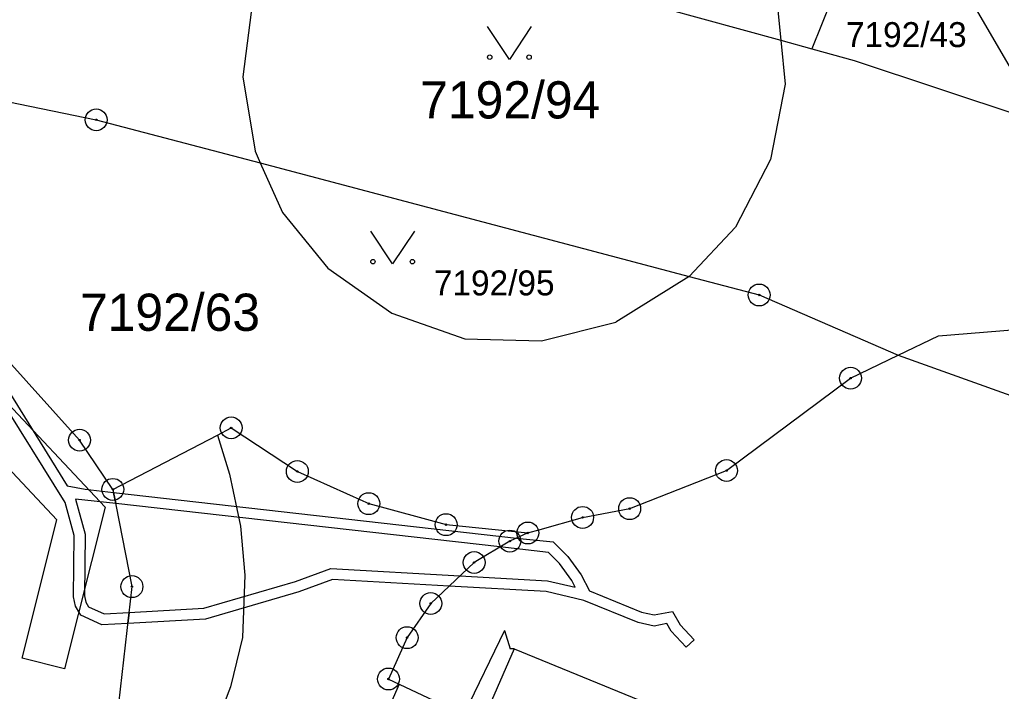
# Model space of a CAD drawing. Extents: x -593183 to -588034, y -1130415 to -1124994.
# Drawn here: x -592144.33 to -592099.52, y -1128222.06 to -1128191.38 of the extents above; entities that cross this region are included whole.
import ezdxf

# ---------------------------------------------------------------- set-up
doc = ezdxf.new("R2010")
doc.units = 0
for name, color, linetype in [('Vrstva 1', 7, 'Continuous'), ('Vrstva 18', 7, 'Continuous'), ('Vrstva 24', 7, 'Continuous'), ('Vrstva 25', 7, 'Continuous'), ('Vrstva 27', 7, 'Continuous'), ('Vrstva 4', 7, 'Continuous')]:
    doc.layers.add(name, color=color, linetype=linetype)

msp = doc.modelspace()

# ---------------------------------------------------------------- linework, layer by layer
at = {"layer": 'Vrstva 1'}
for p, q in [((-592189.56, -1128185.87), (-592140.83, -1128195.96)), ((-592131.54, -1128186.28), (-592109.58, -1128192.33)), ((-592133.68, -1128190.44), (-592134.14, -1128194)), ((-592101.16, -1128190.07), (-592099.01, -1128193.77)), ((-592109.73, -1128190.81), (-592109.58, -1128192.33)), ((-592107.29, -1128190.52), (-592108.17, -1128192.72)), ((-592109.58, -1128192.33), (-592109.39, -1128194.33)), ((-592109.58, -1128192.33), (-592108.17, -1128192.72)), ((-592108.17, -1128192.72), (-592106.24, -1128193.25)), ((-592106.24, -1128193.25), (-592094.48, -1128197.15)), ((-592134.14, -1128194), (-592133.58, -1128197.4)), ((-592109.39, -1128194.33), (-592110.06, -1128197.77)), ((-592140.83, -1128195.96), (-592133.34, -1128197.93)), ((-592133.58, -1128197.4), (-592133.34, -1128197.93)), ((-592133.34, -1128197.93), (-592132.32, -1128200.19)), ((-592133.34, -1128197.93), (-592113.76, -1128203.11)), ((-592110.06, -1128197.77), (-592111.65, -1128200.87)), ((-592132.32, -1128200.19), (-592130.26, -1128202.74)), ((-592111.65, -1128200.87), (-592113.76, -1128203.11)), ((-592130.26, -1128202.74), (-592127.34, -1128204.79)), ((-592113.76, -1128203.11), (-592117.11, -1128205.21)), ((-592113.76, -1128203.11), (-592110.57, -1128203.96)), ((-592110.57, -1128203.96), (-592104.23, -1128206.71)), ((-592127.34, -1128204.79), (-592124.01, -1128205.96)), ((-592120.5, -1128206.05), (-592117.11, -1128205.21)), ((-592099.59, -1128205.6), (-592095.83, -1128205.29)), ((-592102.39, -1128205.83), (-592099.59, -1128205.6)), ((-592124.01, -1128205.96), (-592120.5, -1128206.05)), ((-592104.23, -1128206.71), (-592102.39, -1128205.83)), ((-592141.59, -1128210.59), (-592145.26, -1128206.52)), ((-592106.4, -1128207.76), (-592104.23, -1128206.71)), ((-592104.23, -1128206.71), (-592056.76, -1128223.76)), ((-592112.06, -1128211.98), (-592106.4, -1128207.76)), ((-592135.3, -1128210.36), (-592134.67, -1128210.03)), ((-592134.67, -1128210.03), (-592131.65, -1128212.02)), ((-592140.07, -1128212.84), (-592141.59, -1128210.59)), ((-592140.07, -1128212.84), (-592135.3, -1128210.36)), ((-592135.3, -1128210.36), (-592134.74, -1128212.14)), ((-592131.65, -1128212.02), (-592128.66, -1128213.37)), ((-592116.48, -1128213.72), (-592112.06, -1128211.98)), ((-592134.74, -1128212.14), (-592134.25, -1128214.52)), ((-592140.07, -1128212.84), (-592139.2, -1128217.28)), ((-592128.66, -1128213.37), (-592128.39, -1128213.49)), ((-592128.39, -1128213.49), (-592124.86, -1128214.45)), ((-592118.63, -1128214.12), (-592116.48, -1128213.72)), ((-592120.56, -1128214.67), (-592118.63, -1128214.12)), ((-592134.25, -1128214.52), (-592134.05, -1128216.76)), ((-592124.86, -1128214.45), (-592121.13, -1128214.83)), ((-592121.13, -1128214.83), (-592120.56, -1128214.67)), ((-592121.13, -1128214.83), (-592121.95, -1128215.2)), ((-592121.95, -1128215.2), (-592123.58, -1128216.18)), ((-592123.58, -1128216.18), (-592125.56, -1128218.05)), ((-592134.05, -1128216.76), (-592134.15, -1128219.61)), ((-592139.2, -1128217.28), (-592139.81, -1128222.63)), ((-592125.56, -1128218.05), (-592126.64, -1128219.61)), ((-592134.15, -1128219.61), (-592134.7, -1128221.86)), ((-592126.64, -1128219.61), (-592127.49, -1128221.5)), ((-592122.2, -1128219.29), (-592124.05, -1128223.12)), ((-592122.2, -1128219.29), (-592121.93, -1128220.12)), ((-592121.75, -1128220.12), (-592121.93, -1128220.12)), ((-592121.75, -1128220.12), (-592095.77, -1128230.76)), ((-592134.7, -1128221.86), (-592143.3, -1128243.89)), ((-592127, -1128221.73), (-592128.21, -1128224.48)), ((-592127.49, -1128221.5), (-592127, -1128221.73)), ((-592127, -1128221.73), (-592124.05, -1128223.12))]:
    msp.add_line(p, q, dxfattribs=at)
at = {"layer": 'Vrstva 24'}
for centre, radius in [((-592140.83, -1128195.96), 0.5), ((-592140.83, -1128195.96), 0.0327), ((-592110.57, -1128203.96), 0.5), ((-592110.57, -1128203.96), 0.0327), ((-592106.4, -1128207.76), 0.5), ((-592106.4, -1128207.76), 0.0327), ((-592134.67, -1128210.03), 0.5), ((-592141.59, -1128210.59), 0.5), ((-592134.67, -1128210.03), 0.0327), ((-592141.59, -1128210.59), 0.0327), ((-592131.65, -1128212.02), 0.5), ((-592112.06, -1128211.98), 0.5), ((-592131.65, -1128212.02), 0.0327), ((-592112.06, -1128211.98), 0.0327), ((-592140.07, -1128212.84), 0.5), ((-592140.07, -1128212.84), 0.0327), ((-592128.39, -1128213.49), 0.5), ((-592116.48, -1128213.72), 0.5), ((-592128.39, -1128213.49), 0.0327), ((-592118.63, -1128214.12), 0.5), ((-592116.48, -1128213.72), 0.0327), ((-592124.86, -1128214.45), 0.5), ((-592118.63, -1128214.12), 0.0327), ((-592124.86, -1128214.45), 0.0327), ((-592121.95, -1128215.2), 0.5), ((-592121.13, -1128214.83), 0.5), ((-592121.13, -1128214.83), 0.0327), ((-592121.95, -1128215.2), 0.0327), ((-592123.58, -1128216.18), 0.5), ((-592123.58, -1128216.18), 0.0327), ((-592139.2, -1128217.28), 0.5), ((-592139.2, -1128217.28), 0.0327), ((-592125.56, -1128218.05), 0.5), ((-592125.56, -1128218.05), 0.0327), ((-592126.64, -1128219.61), 0.5), ((-592126.64, -1128219.61), 0.0327), ((-592127.49, -1128221.5), 0.5), ((-592127.49, -1128221.5), 0.0327)]:
    msp.add_circle(centre, radius, dxfattribs=at)
at = {"layer": 'Vrstva 25'}
for points in [[(-592120.97, -1128191.7), (-592121.97, -1128193.2), (-592122.97, -1128191.7)], [(-592126.3, -1128201.04), (-592127.3, -1128202.54), (-592128.3, -1128201.04)]]:
    msp.add_lwpolyline(points, dxfattribs=at)
for centre in [(-592122.87, -1128193.1), (-592121.07, -1128193.1), (-592128.2, -1128202.44), (-592126.4, -1128202.44)]:
    msp.add_circle(centre, 0.1, dxfattribs=at)
at = {"layer": 'Vrstva 27'}
for p, q in [((-592148.83, -1128201.93), (-592142.15, -1128212.67)), ((-592142.25, -1128213.44), (-592149.19, -1128202.29)), ((-592150.22, -1128203.23), (-592140.42, -1128213.65)), ((-592142.62, -1128214.23), (-592151.62, -1128204.65)), ((-592142.15, -1128212.67), (-592141.33, -1128212.83)), ((-592141.33, -1128212.83), (-592140.04, -1128212.98)), ((-592139.94, -1128213.49), (-592141.78, -1128213.29)), ((-592141.78, -1128213.29), (-592141.34, -1128214.88)), ((-592140.04, -1128212.98), (-592139.94, -1128213.49)), ((-592140.04, -1128212.98), (-592121.64, -1128215.06)), ((-592139.94, -1128213.49), (-592140.04, -1128212.98)), ((-592140.42, -1128213.65), (-592142.27, -1128221.03)), ((-592141.84, -1128214.94), (-592142.25, -1128213.44)), ((-592122.4, -1128215.47), (-592139.94, -1128213.49)), ((-592144.21, -1128220.55), (-592142.62, -1128214.23)), ((-592141.86, -1128217.74), (-592141.84, -1128214.94)), ((-592141.34, -1128214.88), (-592141.36, -1128217.7)), ((-592121.64, -1128215.06), (-592119.97, -1128215.24)), ((-592120.19, -1128215.72), (-592122.4, -1128215.47)), ((-592119.97, -1128215.24), (-592119.3, -1128215.9)), ((-592119.68, -1128216.22), (-592120.19, -1128215.72)), ((-592119.3, -1128215.9), (-592118.7, -1128216.74)), ((-592131.74, -1128217.04), (-592130.12, -1128216.46)), ((-592130.12, -1128216.46), (-592124.23, -1128216.79)), ((-592119.12, -1128217), (-592119.68, -1128216.22)), ((-592124.23, -1128216.79), (-592120.23, -1128217.01)), ((-592118.7, -1128216.74), (-592118.32, -1128217.48)), ((-592135.92, -1128218.26), (-592131.74, -1128217.04)), ((-592130.04, -1128216.96), (-592131.58, -1128217.52)), ((-592124.72, -1128217.26), (-592130.04, -1128216.96)), ((-592120.29, -1128217.51), (-592124.72, -1128217.26)), ((-592120.23, -1128217.01), (-592118.97, -1128217.31)), ((-592118.97, -1128217.31), (-592119.12, -1128217)), ((-592141.78, -1128218.17), (-592141.86, -1128217.74)), ((-592141.36, -1128217.7), (-592141.3, -1128217.99)), ((-592131.58, -1128217.52), (-592135.84, -1128218.76)), ((-592118.58, -1128217.92), (-592120.29, -1128217.51)), ((-592118.32, -1128217.48), (-592115.94, -1128218.44)), ((-592141.53, -1128218.58), (-592141.78, -1128218.17)), ((-592141.3, -1128217.99), (-592141.18, -1128218.2)), ((-592141.18, -1128218.2), (-592140.47, -1128218.53)), ((-592139.33, -1128218.46), (-592135.92, -1128218.26)), ((-592116.09, -1128218.92), (-592118.58, -1128217.92)), ((-592140.57, -1128219.03), (-592141.53, -1128218.58)), ((-592140.47, -1128218.53), (-592139.33, -1128218.46)), ((-592139.33, -1128218.46), (-592139.39, -1128218.97)), ((-592139.39, -1128218.97), (-592139.33, -1128218.46)), ((-592115.94, -1128218.44), (-592115.36, -1128218.57)), ((-592115.36, -1128218.57), (-592114.53, -1128218.41)), ((-592114.53, -1128218.41), (-592114.18, -1128219.02)), ((-592139.39, -1128218.97), (-592140.57, -1128219.03)), ((-592135.84, -1128218.76), (-592139.39, -1128218.97)), ((-592115.36, -1128219.08), (-592116.09, -1128218.92)), ((-592114.79, -1128218.97), (-592115.36, -1128219.08)), ((-592114.58, -1128219.32), (-592114.79, -1128218.97)), ((-592114.18, -1128219.02), (-592113.54, -1128219.71)), ((-592113.9, -1128220.05), (-592114.58, -1128219.32)), ((-592113.54, -1128219.71), (-592113.9, -1128220.05)), ((-592142.27, -1128221.03), (-592144.21, -1128220.55))]:
    msp.add_line(p, q, dxfattribs=at)
at = {"layer": 'Vrstva 4'}
msp.add_line((-592121.75, -1128220.12), (-592128.38, -1128235.33), dxfattribs=at)

# ---------------------------------------------------------------- texts
at = {"layer": 'Vrstva 18'}
for s, height, p in [('7192/43', 1.14, (-592106.61, -1128192.64)), ('7192/94', 1.7, (-592126.04, -1128195.9)), ('7192/95', 1.14, (-592125.42, -1128203.98)), ('7192/63', 1.7, (-592141.57, -1128205.6))]:
    msp.add_text(s, height=height, dxfattribs=at).set_placement(p)

doc.saveas('drawing.dxf')
